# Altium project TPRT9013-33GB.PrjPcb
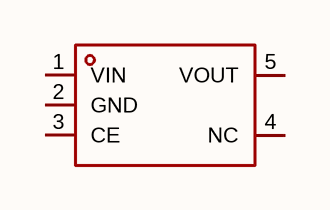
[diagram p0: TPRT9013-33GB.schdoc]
1 sheet, 1 parts. Net scope: global (net labels, ports and power ports of the same name join across sheets).

## Sheet TPRT9013-33GB.schdoc
size 127 x 101 mm

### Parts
U?  tprt9013-33gb  [SOT-23-5_L3.0-W1.7-P0.95-LS2.8-BL]  (value not drawn)

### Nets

Not connected (* = marked no-connect by the designer): U? 1(VIN) 2(GND) 3(CE) 4(NC) 5(VOUT)

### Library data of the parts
U? = tprt9013-33gb: 输出极性:正极;工作电压:7V;输出电压:3.3V;输出电流:500mA;电源纹波抑制比(PSRR):70dB@(1kHz);输出类型:固定;; Manufacturer: TECH PUBLIC(台舟); AddInBom: yes; ModelId: 0a2a1b8f50944f73965918ad6e5fe167; ModelName: SOT-23-5_L2.9-W1.6-H1.1-LS2.8-P0.95; ModelTransform: 118.60433,114.173,0,90,0,0,0.0005,0.0005,0; Output Configuration: 正极; Voltage - Supply: 7V; Output Voltage: 3.3V; Output Current: 500mA; Voltage Dropout: 300mV@(200mA); standby current: 60uA; Noise: 50uVrms; Output Type: 固定; Number of Outputs: 1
